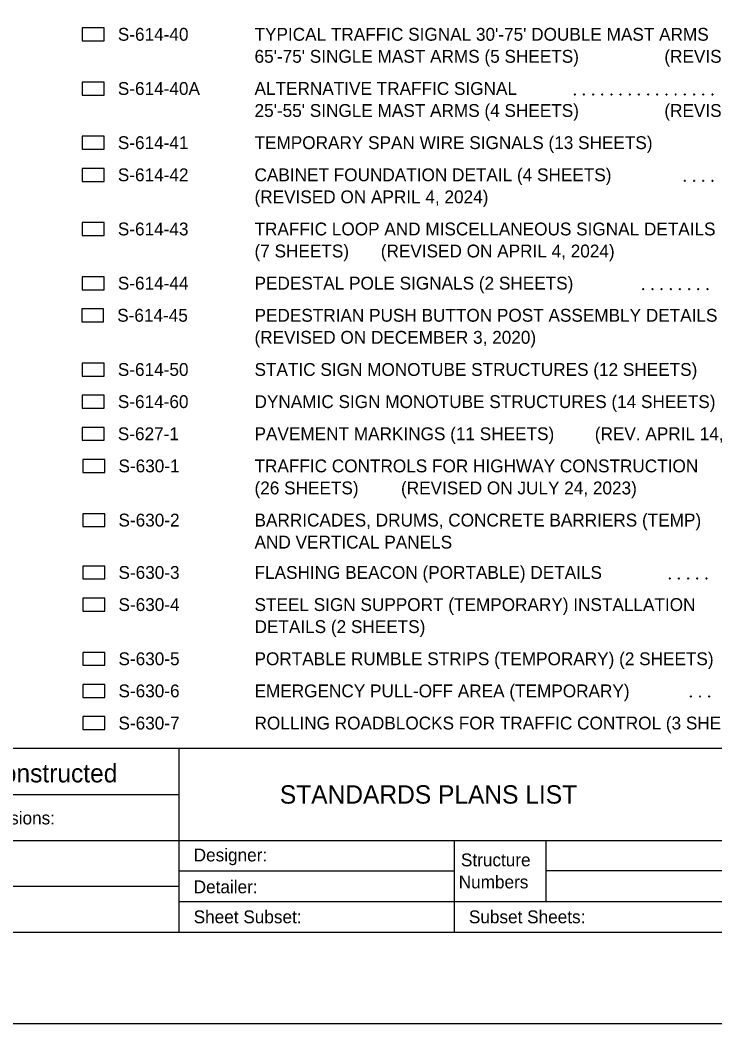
# Model space of a CAD drawing. Extents: x 0 to 1.42, y 0 to 0.92.
# Drawn here: x 0.9418 to 1.2574, y 0 to 0.4557 of the extents above; entities that cross this region are included whole.
import ezdxf

# ---------------------------------------------------------------- set-up
doc = ezdxf.new("R2010")
doc.units = 0
for name, color, linetype in [('DRAFT_Text-Notes', 7, 'Continuous'), ('DRAFT_Text-Titles', 7, 'Continuous'), ('SHEET_Lines', 7, 'Continuous'), ('SHEET_Plot Boundary', 7, 'Continuous'), ('SHEET_Text-Border Info', 7, 'Continuous'), ('SHEET_Text-Titles', 7, 'Continuous')]:
    doc.layers.add(name, color=color, linetype=linetype)

msp = doc.modelspace()

# ---------------------------------------------------------------- linework, layer by layer
at = {"layer": 'DRAFT_Text-Notes'}
for centre in [(1.19372, 0.42188), (1.19789, 0.42188), (1.20206, 0.42188), (1.20622, 0.42188), (1.21039, 0.42188), (1.21456, 0.42188), (1.21872, 0.42188), (1.22289, 0.42188), (1.22706, 0.42188), (1.23122, 0.42188), (1.23539, 0.42188), (1.23956, 0.42188), (1.24372, 0.42188), (1.24789, 0.42188), (1.25206, 0.42188), (1.25622, 0.42188), (1.24372, 0.3827), (1.24789, 0.3827), (1.25206, 0.3827), (1.25622, 0.3827), (1.22482, 0.33351), (1.22899, 0.33351), (1.23316, 0.33351), (1.23732, 0.33351), (1.24149, 0.33351), (1.24566, 0.33351), (1.24982, 0.33351), (1.25399, 0.33351), (1.23686, 0.2022), (1.24102, 0.2022), (1.24519, 0.2022), (1.24936, 0.2022), (1.25352, 0.2022), (1.24645, 0.14866), (1.25061, 0.14866), (1.25478, 0.14866)]:
    msp.add_circle(centre, 0.000208, dxfattribs=at)
for centre, start, end in [((1.19372, 0.42188), 0, 180), ((1.19372, 0.42188), 180, 0), ((1.19789, 0.42188), 0, 180), ((1.19789, 0.42188), 180, 0), ((1.20206, 0.42188), 0, 180), ((1.20206, 0.42188), 180, 0), ((1.20622, 0.42188), 0, 180), ((1.20622, 0.42188), 180, 0), ((1.21039, 0.42188), 0, 180), ((1.21039, 0.42188), 180, 0), ((1.21456, 0.42188), 0, 180), ((1.21456, 0.42188), 180, 0), ((1.21872, 0.42188), 0, 180), ((1.21872, 0.42188), 180, 0), ((1.22289, 0.42188), 0, 180), ((1.22289, 0.42188), 180, 0), ((1.22706, 0.42188), 0, 180), ((1.22706, 0.42188), 180, 0), ((1.23122, 0.42188), 0, 180), ((1.23122, 0.42188), 180, 0), ((1.23539, 0.42188), 0, 180), ((1.23539, 0.42188), 180, 0), ((1.23956, 0.42188), 0, 180), ((1.23956, 0.42188), 180, 0), ((1.24372, 0.42188), 0, 180), ((1.24372, 0.42188), 180, 0), ((1.24789, 0.42188), 0, 180), ((1.24789, 0.42188), 180, 0), ((1.25206, 0.42188), 0, 180), ((1.25206, 0.42188), 180, 0), ((1.25622, 0.42188), 0, 180), ((1.25622, 0.42188), 180, 0), ((1.24372, 0.3827), 0, 180), ((1.24789, 0.3827), 0, 180), ((1.25206, 0.3827), 0, 180), ((1.25622, 0.3827), 0, 180), ((1.24372, 0.3827), 180, 0), ((1.24789, 0.3827), 180, 0), ((1.25206, 0.3827), 180, 0), ((1.25622, 0.3827), 180, 0), ((1.22482, 0.33351), 0, 180), ((1.22482, 0.33351), 180, 0), ((1.22899, 0.33351), 0, 180), ((1.22899, 0.33351), 180, 0), ((1.23316, 0.33351), 0, 180), ((1.23316, 0.33351), 180, 0), ((1.23732, 0.33351), 0, 180), ((1.23732, 0.33351), 180, 0), ((1.24149, 0.33351), 0, 180), ((1.24149, 0.33351), 180, 0), ((1.24566, 0.33351), 0, 180), ((1.24566, 0.33351), 180, 0), ((1.24982, 0.33351), 0, 180), ((1.24982, 0.33351), 180, 0), ((1.25399, 0.33351), 0, 180), ((1.25399, 0.33351), 180, 0), ((1.23686, 0.2022), 0, 180), ((1.23686, 0.2022), 180, 0), ((1.24102, 0.2022), 0, 180), ((1.24102, 0.2022), 180, 0), ((1.24519, 0.2022), 0, 180), ((1.24519, 0.2022), 180, 0), ((1.24936, 0.2022), 0, 180), ((1.24936, 0.2022), 180, 0), ((1.25352, 0.2022), 0, 180), ((1.25352, 0.2022), 180, 0), ((1.24645, 0.14866), 0, 180), ((1.24645, 0.14866), 180, 0), ((1.25061, 0.14866), 0, 180), ((1.25061, 0.14866), 180, 0), ((1.25478, 0.14866), 0, 180), ((1.25478, 0.14866), 180, 0)]:
    msp.add_arc(centre, 0.000208, start, end, dxfattribs=at)
at = {"layer": 'SHEET_Lines'}
for p, q in [((1.01389, 0.125), (1.01389, 0.04167)), ((0.90278, 0.10417), (1.01389, 0.10417)), ((0.90278, 0.08333), (1.375, 0.08333)), ((1.13889, 0.08333), (1.13889, 0.04167)), ((1.18056, 0.08333), (1.18056, 0.05556)), ((1.01389, 0.06944), (1.13889, 0.06944)), ((1.26389, 0.06944), (1.18056, 0.06944)), ((0.90278, 0.0625), (1.01389, 0.0625)), ((1.01389, 0.05556), (1.26389, 0.05556)), ((0.08333, 0.04167), (1.375, 0.04167))]:
    msp.add_line(p, q, dxfattribs=at)
msp.add_lwpolyline([(0.08333, 0.875), (1.375, 0.875), (1.375, 0.125), (0.08333, 0.125)], close=True, dxfattribs=at)
for points in [[(0.97009, 0.44625), (0.98006, 0.44625), (0.98006, 0.45213), (0.97009, 0.45213), (0.97009, 0.44625)], [(0.97009, 0.42165), (0.98006, 0.42165), (0.98006, 0.42754), (0.97009, 0.42754), (0.97009, 0.42165)], [(0.97009, 0.39706), (0.98006, 0.39706), (0.98006, 0.40295), (0.97009, 0.40295), (0.97009, 0.39706)], [(0.97009, 0.38247), (0.98006, 0.38247), (0.98006, 0.38836), (0.97009, 0.38836), (0.97009, 0.38247)], [(0.97009, 0.35788), (0.98006, 0.35788), (0.98006, 0.36376), (0.97009, 0.36376), (0.97009, 0.35788)], [(0.97009, 0.33329), (0.98006, 0.33329), (0.98006, 0.33917), (0.97009, 0.33917), (0.97009, 0.33329)], [(0.9698, 0.31869), (0.97977, 0.31869), (0.97977, 0.32458), (0.9698, 0.32458), (0.9698, 0.31869)], [(0.97009, 0.2941), (0.98006, 0.2941), (0.98006, 0.29999), (0.97009, 0.29999), (0.97009, 0.2941)], [(0.97009, 0.27951), (0.98006, 0.27951), (0.98006, 0.2854), (0.97009, 0.2854), (0.97009, 0.27951)], [(0.97009, 0.26492), (0.98006, 0.26492), (0.98006, 0.2708), (0.97009, 0.2708), (0.97009, 0.26492)], [(0.97038, 0.25033), (0.98035, 0.25033), (0.98035, 0.25621), (0.97038, 0.25621), (0.97038, 0.25033)], [(0.97038, 0.22573), (0.98035, 0.22573), (0.98035, 0.23162), (0.97038, 0.23162), (0.97038, 0.22573)], [(0.97038, 0.20197), (0.98035, 0.20197), (0.98035, 0.20786), (0.97038, 0.20786), (0.97038, 0.20197)], [(0.97038, 0.18738), (0.98035, 0.18738), (0.98035, 0.19326), (0.97038, 0.19326), (0.97038, 0.18738)], [(0.97038, 0.16279), (0.98035, 0.16279), (0.98035, 0.16867), (0.97038, 0.16867), (0.97038, 0.16279)], [(0.97038, 0.14819), (0.98035, 0.14819), (0.98035, 0.15408), (0.97038, 0.15408), (0.97038, 0.14819)], [(0.97038, 0.1336), (0.98035, 0.1336), (0.98035, 0.13949), (0.97038, 0.13949), (0.97038, 0.1336)]]:
    msp.add_lwpolyline(points, dxfattribs=at)
at = {"layer": 'SHEET_Plot Boundary'}
msp.add_lwpolyline([(0, 0.91667), (1.41667, 0.91667), (1.41667, 0), (0, 0)], close=True, dxfattribs=at)

# ---------------------------------------------------------------- texts
at = {"layer": 'DRAFT_Text-Notes'}
for s, height, p in [('S-614-40', 0.005833, (0.98622, 0.4463)), ("TYPICAL TRAFFIC SIGNAL 30'-75' DOUBLE MAST ARMS", 0.0058333, (1.0483, 0.4463)), ("65'-75' SINGLE MAST ARMS (5 SHEETS)", 0.0058333, (1.0483, 0.4363)), ('S-614-40A', 0.005833, (0.98622, 0.42171)), ('ALTERNATIVE TRAFFIC SIGNAL', 0.0058333, (1.0483, 0.42171)), ("25'-55' SINGLE MAST ARMS (4 SHEETS)", 0.0058333, (1.0483, 0.41171)), ('S-614-41', 0.005833, (0.98622, 0.39711)), ('TEMPORARY SPAN WIRE SIGNALS (13 SHEETS)', 0.0058333, (1.0483, 0.39711)), ('S-614-42', 0.005833, (0.98622, 0.38252)), ('CABINET FOUNDATION DETAIL (4 SHEETS)', 0.0058333, (1.0483, 0.38252)), ('S-614-43', 0.005833, (0.98622, 0.35793)), ('TRAFFIC LOOP AND MISCELLANEOUS SIGNAL DETAILS', 0.0058333, (1.0483, 0.35793)), ('(7 SHEETS)', 0.005833, (1.0483, 0.34793)), ('S-614-44', 0.005833, (0.98622, 0.33334)), ('PEDESTAL POLE SIGNALS (2 SHEETS)', 0.0058333, (1.0483, 0.33334)), ('S-614-45', 0.005833, (0.98593, 0.31875)), ('PEDESTRIAN PUSH BUTTON POST ASSEMBLY DETAILS (6 SHEETS)', 0.0058333, (1.0483, 0.31875)), ('S-614-50', 0.005833, (0.98622, 0.29415)), ('STATIC SIGN MONOTUBE STRUCTURES (12 SHEETS)', 0.0058333, (1.0483, 0.29415)), ('S-614-60', 0.005833, (0.98622, 0.27956)), ('DYNAMIC SIGN MONOTUBE STRUCTURES (14 SHEETS)', 0.0058333, (1.0483, 0.27956)), ('S-627-1', 0.005833, (0.98622, 0.26497)), ('PAVEMENT MARKINGS (11 SHEETS)', 0.0058333, (1.0483, 0.26497)), ('S-630-1', 0.005833, (0.98651, 0.25038)), ('TRAFFIC CONTROLS FOR HIGHWAY CONSTRUCTION', 0.0058333, (1.0483, 0.25038)), ('(26 SHEETS)', 0.0058333, (1.0483, 0.24038)), ('S-630-2', 0.005833, (0.98651, 0.22579)), ('BARRICADES, DRUMS, CONCRETE BARRIERS (TEMP)', 0.0058333, (1.0483, 0.22579)), ('AND VERTICAL PANELS', 0.0058333, (1.0483, 0.21579)), ('S-630-3', 0.005833, (0.98651, 0.20202)), ('FLASHING BEACON (PORTABLE) DETAILS', 0.0058333, (1.0483, 0.20202)), ('S-630-4', 0.005833, (0.98651, 0.18743)), ('STEEL SIGN SUPPORT (TEMPORARY) INSTALLATION', 0.0058333, (1.0483, 0.18743)), ('DETAILS (2 SHEETS)', 0.0058333, (1.0483, 0.17743)), ('S-630-5', 0.005833, (0.98651, 0.16284)), ('PORTABLE RUMBLE STRIPS (TEMPORARY) (2 SHEETS)', 0.0058333, (1.0483, 0.16284)), ('S-630-6', 0.005833, (0.98651, 0.14825)), ('EMERGENCY PULL-OFF AREA (TEMPORARY)', 0.0058333, (1.0483, 0.14825)), ('S-630-7', 0.005833, (0.98651, 0.13365)), ('ROLLING ROADBLOCKS FOR TRAFFIC CONTROL (3 SHEETS)', 0.0058333, (1.0483, 0.13365))]:
    msp.add_text(s, height=height, dxfattribs=at).set_placement(p)
at = {"layer": 'DRAFT_Text-Titles'}
for s, p in [('(REVISED ON JULY 22, 2022)', (1.23442, 0.4363)), ('(REVISED ON JULY 22, 2022)', (1.23442, 0.41171)), ('(REVISED ON APRIL 4, 2024)', (1.0483, 0.37252)), ('(REVISED ON APRIL 4, 2024)', (1.10563, 0.34793)), ('(REVISED ON DECEMBER 3, 2020)', (1.0483, 0.30875)), ('(REV. APRIL 14, 2023)', (1.20283, 0.26497)), ('(REVISED ON JULY 24, 2023)', (1.11483, 0.24038))]:
    msp.add_text(s, height=0.0058333, dxfattribs=at).set_placement(p)
at = {"layer": 'SHEET_Text-Border Info'}
for s, height, p in [('No Revisions:', 0.0058333, (0.90955, 0.09056)), ('Designer:', 0.005833, (1.02066, 0.07377)), ('Structure', 0.005833, (1.14203, 0.07153)), ('Detailer:', 0.005833, (1.02066, 0.05931)), ('Numbers', 0.005833, (1.14103, 0.06153)), ('Sheet Subset:', 0.0058333, (1.02066, 0.04569)), ('Subset Sheets:', 0.0058333, (1.14566, 0.04569))]:
    msp.add_text(s, height=height, dxfattribs=at).set_placement(p)
at = {"layer": 'SHEET_Text-Titles'}
for s, p in [('As Constructed', (0.90984, 0.10964)), ('STANDARDS PLANS LIST', (1.0598, 0.1))]:
    msp.add_text(s, height=0.0083333, dxfattribs=at).set_placement(p)

doc.saveas('drawing.dxf')
